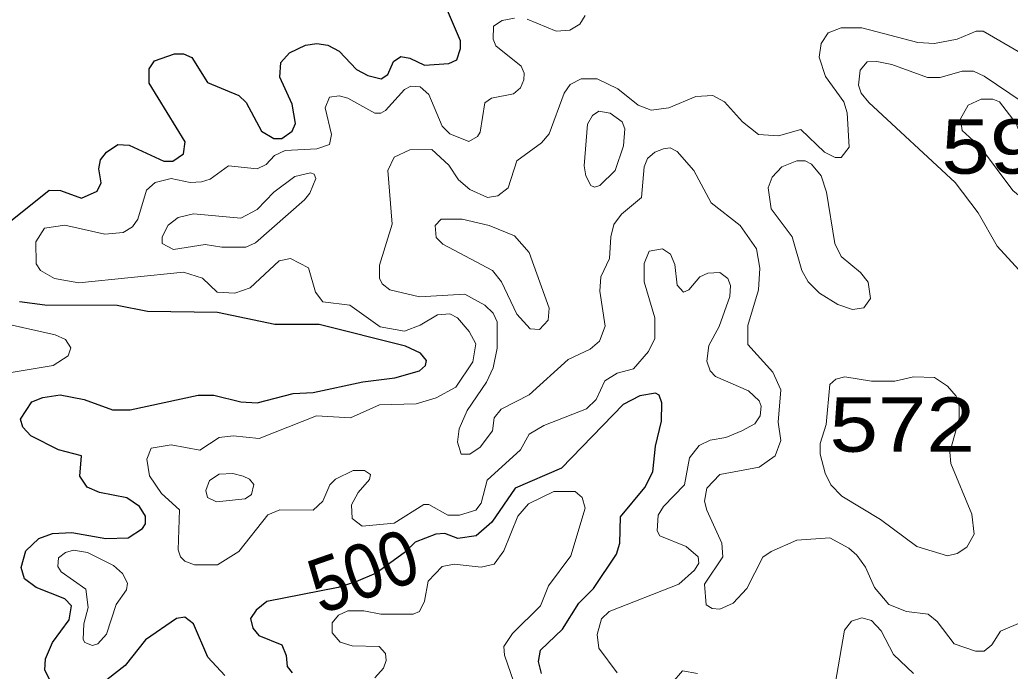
# Model space of a CAD drawing. Extents: x 577 to 602.9, y 7483.8 to 7511.6.
# Drawn here: x 587.677 to 589.135, y 7498.952 to 7499.911 of the extents above; entities that cross this region are included whole.
import ezdxf
from ezdxf.enums import TextEntityAlignment as Align

# ---------------------------------------------------------------- set-up
doc = ezdxf.new("R2010")
doc.units = 0
doc.header["$LTSCALE"] = 0.032
doc.layers.add('1', color=7, linetype='Continuous', lineweight=25)
doc.layers.add('2', color=7, linetype='Continuous', lineweight=13)
doc.layers.add('61', color=7, linetype='Continuous')

msp = doc.modelspace()

# ---------------------------------------------------------------- linework, layer by layer
at = {"layer": '1'}
for points in [[(587.6628, 7499.6141), (587.72, 7499.6602), (587.7367, 7499.6594), (587.7677, 7499.6483), (587.7908, 7499.6586), (587.7964, 7499.6706), (587.7932, 7499.6912), (587.7956, 7499.7048), (587.8043, 7499.7159), (587.821, 7499.727), (587.8377, 7499.7262), (587.8886, 7499.7024), (587.9021, 7499.7024), (587.918, 7499.7135), (587.9204, 7499.731), (587.8671, 7499.8177), (587.8671, 7499.8384), (587.8751, 7499.8503), (587.9045, 7499.8606), (587.918, 7499.8606), (587.93, 7499.8551), (587.953, 7499.8185), (587.9991, 7499.7994), (588.0103, 7499.7891), (588.0325, 7499.7469), (588.0508, 7499.7358), (588.0627, 7499.7358), (588.0779, 7499.7469), (588.0826, 7499.758), (588.0779, 7499.7867), (588.0596, 7499.8264), (588.0612, 7499.8479), (588.0739, 7499.8622), (588.0977, 7499.8733), (588.1144, 7499.8757), (588.1303, 7499.8733), (588.147, 7499.8646), (588.1725, 7499.8376), (588.1892, 7499.8288), (588.2091, 7499.824), (588.2186, 7499.8304), (588.2273, 7499.8495), (588.2377, 7499.8566), (588.2512, 7499.8543), (588.2727, 7499.8439), (588.3085, 7499.8463), (588.3204, 7499.8519), (588.3259, 7499.8686), (588.3259, 7499.8797), (588.3021, 7499.9346)], [(588.2655, 7499.3938), (588.2743, 7499.4018), (588.2759, 7499.409), (588.2671, 7499.4201), (588.2448, 7499.4305), (588.1176, 7499.4622), (588.0524, 7499.4622), (587.9681, 7499.4797), (587.8647, 7499.4813), (587.8202, 7499.4901), (587.7137, 7499.4909), (587.6763, 7499.4956)], [(587.7208, 7498.939), (587.7137, 7498.9533), (587.7145, 7498.97), (587.7248, 7498.9939), (587.7494, 7499.0273), (587.7526, 7499.0479), (587.7431, 7499.0583), (587.7009, 7499.075), (587.6834, 7499.0877), (587.6787, 7499.1044), (587.6858, 7499.1291), (587.7049, 7499.1473), (587.7248, 7499.1545), (587.7534, 7499.1561), (587.8035, 7499.1473), (587.8361, 7499.1481), (587.8576, 7499.1617), (587.8616, 7499.1688), (587.8616, 7499.1799), (587.8528, 7499.1943), (587.8345, 7499.207), (587.794, 7499.2149), (587.7757, 7499.2229), (587.7653, 7499.2388), (587.7677, 7499.269), (587.7335, 7499.2778), (587.693, 7499.2984), (587.6811, 7499.3112), (587.6779, 7499.3231), (587.6946, 7499.3485), (587.7105, 7499.3549), (587.7359, 7499.3589), (587.7717, 7499.3517), (587.8131, 7499.3366), (587.8393, 7499.3366), (587.9395, 7499.3581), (587.9626, 7499.3581), (588.0023, 7499.3485), (588.0262, 7499.3469), (588.0794, 7499.3605), (588.1089, 7499.362), (588.182, 7499.3779), (588.2289, 7499.3835), (588.2655, 7499.3938)], [(588.4452, 7498.9486), (588.4405, 7498.966), (588.4436, 7498.9827), (588.4762, 7499.0138), (588.5001, 7499.0519), (588.5216, 7499.0734), (588.5558, 7499.1243), (588.5605, 7499.1402), (588.5613, 7499.1792), (588.5971, 7499.2221), (588.609, 7499.2452), (588.613, 7499.2833), (588.6218, 7499.3199), (588.6225, 7499.3469), (588.6186, 7499.3581), (588.613, 7499.3612), (588.5899, 7499.3573)], [(588.5899, 7499.3573), (588.5653, 7499.3445), (588.4746, 7499.2507), (588.4063, 7499.2213), (588.3721, 7499.1712), (588.349, 7499.1513), (588.322, 7499.1473), (588.3029, 7499.1545), (588.2894, 7499.1537), (588.2592, 7499.1418), (588.2429, 7499.1259), (588.2014, 7499.0963), (588.1714, 7499.0835), (588.1456, 7499.0749), (588.0405, 7499.0543), (588.0246, 7499.0416), (588.0166, 7499.0297), (588.0198, 7499.0153), (588.0286, 7499.0042), (588.0627, 7498.9907), (588.0691, 7498.9748), (588.0707, 7498.9589), (588.0779, 7498.9493)], [(587.9785, 7498.9454), (587.9538, 7498.9724), (587.9323, 7499.0217), (587.9196, 7499.0312), (587.9077, 7499.0297), (587.8616, 7498.9979), (587.8321, 7498.9605), (587.8051, 7498.939)]]:
    msp.add_lwpolyline(points, dxfattribs=at)
at = {"layer": '2'}
for points in [[(588.4238, 7499.9115), (588.4667, 7499.894), (588.4866, 7499.8956), (588.5017, 7499.9044), (588.5096, 7499.9171)], [(588.1677, 7499.2475), (588.1415, 7499.2348), (588.1335, 7499.2261), (588.1232, 7499.2022), (588.1089, 7499.1887), (588.0596, 7499.1895), (588.0421, 7499.1823), (587.9991, 7499.1283), (587.9681, 7499.1084), (587.9339, 7499.1084), (587.9196, 7499.1139), (587.9133, 7499.1203), (587.9101, 7499.1306), (587.9117, 7499.1895), (587.8854, 7499.2133), (587.8679, 7499.2396), (587.864, 7499.2642), (587.8703, 7499.2801), (587.8997, 7499.2849), (587.9419, 7499.277), (587.9705, 7499.296), (587.9912, 7499.2984), (588.0293, 7499.2945), (588.1136, 7499.3278), (588.1637, 7499.3247), (588.2067, 7499.3438), (588.2607, 7499.3453), (588.2902, 7499.3541), (588.3188, 7499.37), (588.3442, 7499.4074), (588.3482, 7499.4336), (588.3387, 7499.4519), (588.3212, 7499.4718), (588.31, 7499.4781), (588.2918, 7499.4765), (588.2663, 7499.4614), (588.2435, 7499.4524), (588.2075, 7499.4588), (588.1629, 7499.4909), (588.1232, 7499.4956), (588.112, 7499.5099), (588.1017, 7499.5457), (588.0755, 7499.5592), (588.0588, 7499.5561), (588.0158, 7499.5163), (587.9936, 7499.5084), (587.9673, 7499.5099), (587.9459, 7499.5306), (587.918, 7499.5394), (587.7638, 7499.5235), (587.728, 7499.5298), (587.7073, 7499.5418), (587.7009, 7499.5513), (587.7001, 7499.5839), (587.7129, 7499.6038), (587.7431, 7499.6085), (587.8019, 7499.595), (587.829, 7499.5974), (587.8425, 7499.6062), (587.8504, 7499.6173), (587.8632, 7499.6602), (587.8759, 7499.6714), (587.8997, 7499.6769), (587.9276, 7499.6714), (587.9443, 7499.6722), (587.957, 7499.6761), (587.984, 7499.696), (588.0262, 7499.6912), (588.0397, 7499.6976), (588.0516, 7499.7111), (588.0675, 7499.7183), (588.1144, 7499.7207), (588.1327, 7499.727), (588.1359, 7499.7421), (588.1264, 7499.7811), (588.1327, 7499.797), (588.147, 7499.7986), (588.1598, 7499.7954), (588.1995, 7499.7731), (588.2083, 7499.7731), (588.2154, 7499.7771), (588.2432, 7499.8081), (588.2528, 7499.8129), (588.2663, 7499.8121), (588.279, 7499.801), (588.2989, 7499.7541), (588.31, 7499.7429), (588.3379, 7499.7318), (588.3506, 7499.739), (588.3546, 7499.7453), (588.3617, 7499.7883), (588.3713, 7499.7954), (588.4039, 7499.8018), (588.4142, 7499.8105), (588.419, 7499.8224), (588.4198, 7499.832), (588.415, 7499.8423), (588.3776, 7499.8725), (588.3737, 7499.8821), (588.3745, 7499.9012), (588.3872, 7499.9099)], [(588.3872, 7499.9099), (588.4055, 7499.9131)], [(589.1657, 7499.8535), (589.0957, 7499.894), (589.0853, 7499.894), (589.0575, 7499.8821), (589.0241, 7499.8757), (588.9995, 7499.8773), (588.9168, 7499.8988), (588.8865, 7499.8988), (588.8675, 7499.8916), (588.8571, 7499.8757), (588.8539, 7499.8558), (588.8635, 7499.8272), (588.8905, 7499.7898), (588.8953, 7499.7739), (588.8985, 7499.7231), (588.8865, 7499.7079), (588.8778, 7499.7079), (588.8619, 7499.7159), (588.8269, 7499.7493), (588.7943, 7499.7398), (588.7649, 7499.7421), (588.741, 7499.7604), (588.7148, 7499.7898), (588.6973, 7499.7994), (588.6726, 7499.7978), (588.6329, 7499.7811), (588.6066, 7499.7779), (588.5876, 7499.7851), (588.5573, 7499.8089), (588.5271, 7499.824), (588.5033, 7499.824), (588.4874, 7499.8153), (588.4786, 7499.8026), (588.4564, 7499.7429), (588.4452, 7499.7294), (588.4086, 7499.7032), (588.3959, 7499.6634), (588.3808, 7499.6515), (588.3657, 7499.6491), (588.3395, 7499.661), (588.3228, 7499.6753), (588.3085, 7499.6968), (588.2838, 7499.7199), (588.2512, 7499.7191), (588.2281, 7499.7087), (588.2186, 7499.6889), (588.225, 7499.6101), (588.2067, 7499.5497), (588.2067, 7499.5306), (588.2106, 7499.5219), (588.2218, 7499.5131), (588.2655, 7499.5028), (588.3323, 7499.5068), (588.3617, 7499.4909), (588.3737, 7499.4789), (588.38, 7499.4662), (588.38, 7499.4272), (588.3737, 7499.3986), (588.3641, 7499.3772), (588.3355, 7499.3358), (588.3236, 7499.3088), (588.3212, 7499.2889), (588.3267, 7499.2714), (588.3395, 7499.2714), (588.3546, 7499.2817), (588.3729, 7499.3056), (588.3752, 7499.3247), (588.3856, 7499.3374), (588.4269, 7499.3589), (588.4842, 7499.4105), (588.5168, 7499.4257), (588.5303, 7499.4376)], [(589.1529, 7499.7898), (589.0973, 7499.828), (589.0814, 7499.8352), (589.0647, 7499.8352), (589.0321, 7499.8256), (589.0138, 7499.8256), (588.9613, 7499.8447), (588.939, 7499.8495), (588.9247, 7499.8487), (588.9144, 7499.8368), (588.912, 7499.8145), (588.916, 7499.8026), (588.9271, 7499.7891), (589.0543, 7499.6714), (589.0885, 7499.6268), (589.1164, 7499.5775), (589.1482, 7499.5425)], [(588.5303, 7499.4376), (588.5391, 7499.4598), (588.5311, 7499.5115), (588.5327, 7499.5322), (588.5454, 7499.5592), (588.547, 7499.5911), (588.5518, 7499.6093), (588.5629, 7499.6245), (588.5923, 7499.6491), (588.5963, 7499.6944), (588.6011, 7499.7064), (588.6122, 7499.7159), (588.6249, 7499.7207), (588.6345, 7499.7223), (588.6448, 7499.7167), (588.6695, 7499.6889), (588.6949, 7499.6411), (588.7378, 7499.6078), (588.7617, 7499.5736), (588.7665, 7499.5449), (588.7649, 7499.5131), (588.749, 7499.4606), (588.749, 7499.4328), (588.7856, 7499.3923), (588.7975, 7499.366), (588.7935, 7499.3183), (588.7975, 7499.2913), (588.7895, 7499.269), (588.7657, 7499.2523), (588.7076, 7499.2412), (588.6885, 7499.2213), (588.6854, 7499.2022), (588.6885, 7499.1887), (588.7108, 7499.1402), (588.7124, 7499.1203), (588.6854, 7499.0798), (588.6878, 7499.0495), (588.6965, 7499.044), (588.7076, 7499.0432), (588.7275, 7499.0519), (588.7474, 7499.0734), (588.7712, 7499.1195), (588.7832, 7499.1283), (588.8213, 7499.145), (588.8698, 7499.1481), (588.8977, 7499.133), (588.9096, 7499.1227), (588.9223, 7499.1052), (588.9358, 7499.075), (588.9565, 7499.0503), (588.9828, 7499.04), (589.0146, 7499.036), (589.0281, 7499.0249), (589.0527, 7498.9923), (589.0845, 7498.9812), (589.0973, 7498.9812), (589.1084, 7498.9907), (589.1211, 7499.0106), (589.1545, 7499.0249)], [(588.5565, 7498.9493), (588.5295, 7498.9859), (588.5271, 7499.0058), (588.5335, 7499.0289), (588.5446, 7499.04), (588.6472, 7499.0798), (588.6703, 7499.1004), (588.6766, 7499.1108), (588.6758, 7499.1203), (588.6583, 7499.1354), (588.6194, 7499.1513), (588.6154, 7499.1585), (588.617, 7499.1815), (588.6249, 7499.1943), (588.6559, 7499.2261), (588.6631, 7499.2658), (588.6774, 7499.2841), (588.6933, 7499.2921), (588.7164, 7499.296), (588.7402, 7499.3056), (588.7593, 7499.3159), (588.7673, 7499.3278), (588.7689, 7499.3422), (588.7657, 7499.3501), (588.7498, 7499.3644), (588.7013, 7499.3859), (588.6933, 7499.3938), (588.6885, 7499.4082), (588.6917, 7499.4312), (588.7068, 7499.4591), (588.7227, 7499.5036), (588.7235, 7499.5195), (588.7196, 7499.5298), (588.7076, 7499.5386), (588.6901, 7499.5378), (588.6782, 7499.5322), (588.6623, 7499.5131), (588.6544, 7499.5099), (588.6448, 7499.5203), (588.6416, 7499.5505), (588.6353, 7499.5656), (588.6233, 7499.5736), (588.6035, 7499.5704), (588.5963, 7499.5521), (588.5963, 7499.5251), (588.6122, 7499.4718), (588.6122, 7499.4416), (588.6027, 7499.4225), (588.5804, 7499.397), (588.5565, 7499.3907), (588.5383, 7499.3795), (588.5255, 7499.3517), (588.5112, 7499.3382), (588.4484, 7499.3135), (588.4269, 7499.3008), (588.4142, 7499.2778), (588.3649, 7499.2332), (588.3562, 7499.199), (588.3482, 7499.1887), (588.3244, 7499.1815), (588.3069, 7499.1815), (588.279, 7499.1974), (588.2719, 7499.1974), (588.2281, 7499.1696), (588.1812, 7499.1656), (588.1661, 7499.1768), (588.1653, 7499.1966), (588.1749, 7499.2149), (588.1916, 7499.234), (588.1932, 7499.2412), (588.1844, 7499.2475), (588.1677, 7499.2475)], [(587.6103, 7499.3827), (587.7256, 7499.4018), (587.7479, 7499.4161), (587.7518, 7499.428), (587.7439, 7499.44), (587.7288, 7499.4471), (587.6278, 7499.4694)], [(588.4086, 7498.9231), (588.3904, 7498.9756), (588.3896, 7498.9883), (588.4023, 7499.0074), (588.4436, 7499.0479), (588.4556, 7499.0774), (588.4882, 7499.1219), (588.5096, 7499.1919), (588.5049, 7499.2078), (588.4945, 7499.2165), (588.4635, 7499.2165), (588.4261, 7499.1982), (588.4102, 7499.1799), (588.3896, 7499.1291), (588.3752, 7499.1092), (588.3562, 7499.1052), (588.3164, 7499.1092), (588.2989, 7499.106), (588.2782, 7499.0845), (588.2727, 7499.0551), (588.2655, 7499.04), (588.256, 7499.036), (588.2083, 7499.036)], [(588.2083, 7499.036), (588.1836, 7499.0408), (588.1598, 7499.0408), (588.1462, 7499.0344), (588.1367, 7499.0233), (588.1367, 7499.0082), (588.1486, 7498.9947), (588.1661, 7498.9891), (588.2059, 7498.9883), (588.2154, 7498.978), (588.2162, 7498.9676), (588.2122, 7498.9565), (588.1995, 7498.9422)], [(588.9931, 7498.9486), (588.9637, 7498.9764), (588.9454, 7499.0114), (588.9311, 7499.0265), (588.9168, 7499.0305), (588.9017, 7499.0257), (588.8913, 7499.0122), (588.8778, 7498.9326)], [(588.675, 7498.9486), (588.6528, 7498.9525), (588.6377, 7498.935)]]:
    msp.add_lwpolyline(points, dxfattribs=at)
for points in [[(589.1617, 7499.7127), (589.1649, 7499.665), (589.1609, 7499.6499), (589.1529, 7499.6483), (589.1394, 7499.6594), (589.0917, 7499.7231), (589.0647, 7499.7477), (589.0623, 7499.7652), (589.0734, 7499.7851), (589.0925, 7499.7938), (589.11, 7499.7938), (589.1195, 7499.7898), (589.1442, 7499.758)], [(588.508, 7499.696), (588.5104, 7499.6809), (588.5176, 7499.6666), (588.5232, 7499.6642), (588.5311, 7499.6666), (588.5534, 7499.6889), (588.5661, 7499.7254), (588.5677, 7499.7501), (588.5637, 7499.7604), (588.5462, 7499.7731), (588.5295, 7499.7763), (588.52, 7499.77), (588.5128, 7499.7572)], [(588.8142, 7499.5911), (588.8285, 7499.5418), (588.838, 7499.5251), (588.8547, 7499.5084), (588.8818, 7499.4917), (588.9032, 7499.4845), (588.9199, 7499.4869), (588.9295, 7499.5004), (588.9263, 7499.5243), (588.9152, 7499.5386), (588.8865, 7499.5624), (588.877, 7499.5815), (588.8651, 7499.6571), (588.8571, 7499.6809), (588.8428, 7499.6984), (588.8333, 7499.7032), (588.8213, 7499.7032), (588.7991, 7499.6944), (588.7848, 7499.6793), (588.7792, 7499.6634), (588.7832, 7499.6324)], [(588.1128, 7499.6769), (588.1105, 7499.6833), (588.1049, 7499.6857), (588.0818, 7499.6801), (588.0508, 7499.6571), (588.0262, 7499.6316), (588.0023, 7499.6189), (587.9323, 7499.6252), (587.9101, 7499.6197), (587.895, 7499.6085), (587.8862, 7499.5911), (587.8862, 7499.5815), (587.9029, 7499.5728), (587.9498, 7499.5799), (587.9745, 7499.5759), (588.0095, 7499.5759), (588.0238, 7499.5823), (588.0961, 7499.6459), (588.1041, 7499.6555)], [(588.3681, 7499.6078), (588.4055, 7499.5926), (588.4269, 7499.568), (588.4564, 7499.4861), (588.4548, 7499.4686), (588.442, 7499.4551), (588.4285, 7499.4559), (588.4086, 7499.4773), (588.3864, 7499.5251), (588.3729, 7499.5418), (588.2997, 7499.5807), (588.2902, 7499.5903), (588.2886, 7499.6078), (588.2973, 7499.6173), (588.3283, 7499.6173)], [(589.0559, 7499.3565), (589.0432, 7499.3716), (589.0241, 7499.3843), (588.9931, 7499.3851), (588.9653, 7499.3787), (588.9311, 7499.3787), (588.8921, 7499.3851), (588.8786, 7499.3819), (588.8698, 7499.374), (588.8643, 7499.3151), (588.8555, 7499.2873), (588.8555, 7499.2714), (588.8627, 7499.2436), (588.8714, 7499.2261), (588.8873, 7499.2094), (588.9446, 7499.1752), (588.9979, 7499.1354), (589.0432, 7499.1219), (589.0575, 7499.1251), (589.0718, 7499.1346), (589.0822, 7499.1537), (589.079, 7499.1831), (589.0482, 7499.2574), (589.0464, 7499.2741), (589.0601, 7499.3233), (589.0601, 7499.3418)], [(588.0055, 7499.2388), (588.015, 7499.2348), (588.0214, 7499.2269), (588.0182, 7499.2118), (588.0087, 7499.2054), (587.9665, 7499.2014), (587.953, 7499.2078), (587.9506, 7499.2181), (587.9562, 7499.2324), (587.9705, 7499.242), (587.9904, 7499.2428)], [(587.7741, 7499.0726), (587.7773, 7499.0456), (587.7709, 7499.0217), (587.7701, 7498.9986), (587.7725, 7498.9939), (587.7836, 7498.9899), (587.7916, 7498.9923), (587.8043, 7499.0066), (587.8186, 7499.0503), (587.8337, 7499.0718), (587.8353, 7499.0813), (587.8282, 7499.0957), (587.8146, 7499.1076), (587.7765, 7499.1267), (587.7558, 7499.1299), (587.7439, 7499.1267), (587.7335, 7499.1187), (587.7327, 7499.106), (587.7375, 7499.098)]]:
    msp.add_lwpolyline(points, close=True, dxfattribs=at)

# ---------------------------------------------------------------- texts
at = {"layer": '61', "width": 1.2}
for s, p in [('592', (589.1412, 7499.6842)), ('572', (588.9764, 7499.2749))]:
    msp.add_text(s, height=0.08, dxfattribs=at).set_placement(p, align=Align.CENTER)
at = {"layer": '61', "width": 0.9}
msp.add_text('500', height=0.08, rotation=19.161, dxfattribs=at).set_placement((588.1957, 7499.0616), align=Align.CENTER)

doc.saveas('drawing.dxf')
